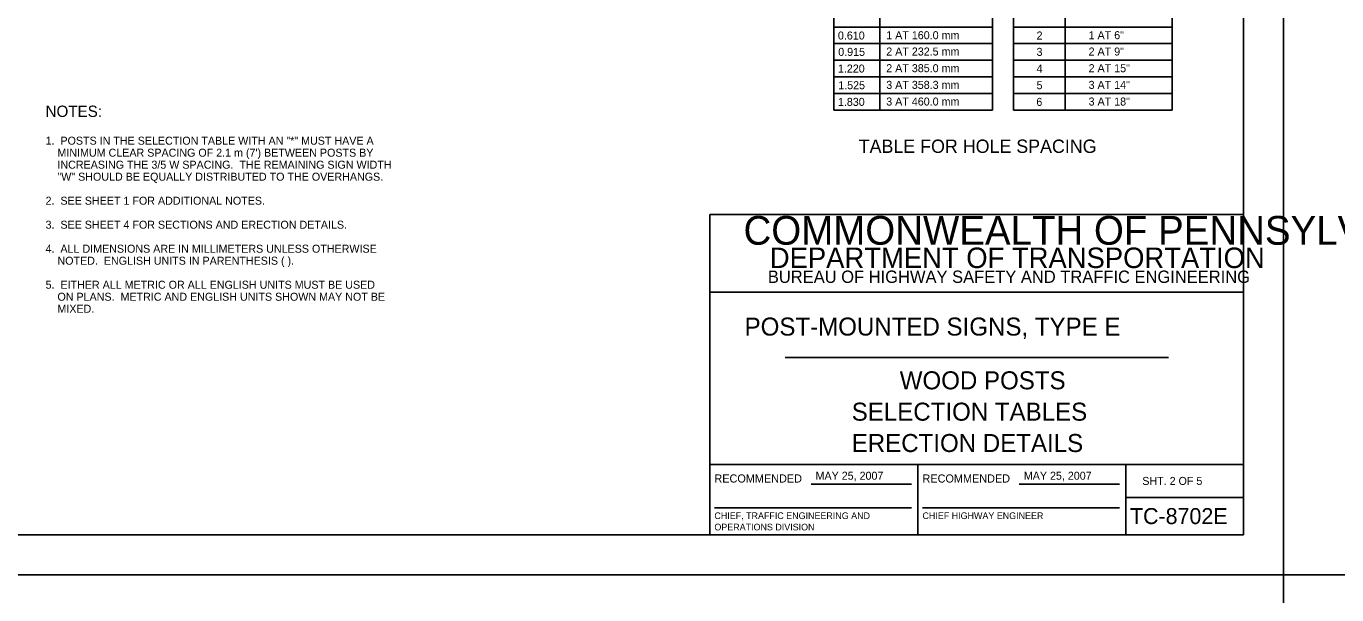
# Model space of a CAD drawing. Extents: x -1958 to 628, y -879 to 309.
# Drawn here: x -747.7 to -256.4, y -292.1 to -78.9 of the extents above; entities that cross this region are included whole.
import ezdxf

# ---------------------------------------------------------------- set-up
doc = ezdxf.new("R2010")
doc.units = 0
for name, color, linetype in [('1', 7, 'Continuous'), ('2', 7, 'Continuous'), ('3', 7, 'Continuous'), ('4', 7, 'Continuous'), ('PLT-BNDY', 7, 'Continuous')]:
    doc.layers.add(name, color=color, linetype=linetype)

msp = doc.modelspace()

# ---------------------------------------------------------------- linework, layer by layer
at = {"layer": '1'}
for p, q in [((-291.39, -269.56), (-291.39, 294.44)), ((-491.39, -269.56), (-491.39, -149.56)), ((-491.39, -149.56), (-291.39, -149.56)), ((-291.39, -178.56), (-491.39, -178.56)), ((-463.14, -203.06), (-319.51, -203.06)), ((-491.39, -243.19), (-291.39, -243.19)), ((-413.39, -243.19), (-413.39, -269.56)), ((-335.51, -269.56), (-335.51, -243.19)), ((-453.45, -250.62), (-415.83, -250.62)), ((-375.45, -250.62), (-337.83, -250.62)), ((-489.7, -259.51), (-415.83, -259.51)), ((-411.7, -259.51), (-337.83, -259.51)), ((-335.51, -255.56), (-291.39, -255.56)), ((-291.39, -269.56), (-1077.39, -269.56)), ((-1077.39, -269.56), (-491.39, -269.56))]:
    msp.add_line(p, q, dxfattribs=at)
at = {"layer": '2'}
for p, q in [((-444.9, -110.4), (-444.9, -60.53)), ((-385.4, -110.4), (-385.4, -60.53)), ((-377.63, -110.4), (-377.63, -60.53)), ((-318.13, -110.4), (-318.13, -60.53)), ((-427.65, -110.4), (-427.65, -73.03)), ((-358.24, -110.4), (-358.24, -73.03)), ((-385.4, -79.28), (-444.9, -79.28)), ((-318.13, -79.28), (-377.63, -79.28)), ((-385.4, -85.4), (-444.9, -85.4)), ((-318.13, -85.4), (-377.63, -85.4)), ((-385.4, -91.65), (-444.9, -91.65)), ((-318.13, -91.65), (-377.63, -91.65)), ((-385.4, -97.9), (-444.9, -97.9)), ((-318.13, -97.9), (-377.63, -97.9)), ((-385.4, -104.15), (-444.9, -104.15)), ((-318.13, -104.15), (-377.63, -104.15)), ((-385.4, -110.4), (-444.9, -110.4)), ((-318.13, -110.4), (-377.63, -110.4))]:
    msp.add_line(p, q, dxfattribs=at)
at = {"layer": 'PLT-BNDY'}
for points in [[(-1117.39, 309.44), (-276.39, 309.44), (-276.39, -284.56), (-1117.39, -284.56)], [(-276.39, 309.44), (564.61, 309.44), (564.61, -284.56), (-276.39, -284.56)], [(-1117.39, -284.56), (-276.39, -284.56), (-276.39, -878.56), (-1117.39, -878.56)]]:
    msp.add_lwpolyline(points, close=True, dxfattribs=at)

# ---------------------------------------------------------------- texts
at = {"layer": '1'}
for s, height, p in [('COMMONWEALTH OF PENNSYLVANIA', 10.7827, (-478.79, -160.83)), ('DEPARTMENT OF TRANSPORTATION', 7.6838, (-468.93, -169.58)), ('BUREAU OF HIGHWAY SAFETY AND TRAFFIC ENGINEERING', 4.6252, (-469.66, -175.15)), ('POST-MOUNTED SIGNS, TYPE E', 6.7492, (-478.39, -194.89)), ('WOOD POSTS', 6.75, (-420.23, -215.04)), ('SELECTION TABLES', 6.75, (-438.23, -226.79)), ('ERECTION DETAILS', 6.75, (-438.23, -238.54)), ('RECOMMENDED', 3.048, (-489.7, -249.99)), ('RECOMMENDED', 3.048, (-411.7, -249.99)), ('SHT. 2 OF 5', 3, (-329.3, -250.88)), ('TC-8702E', 6, (-333.91, -265.56)), ('CHIEF, TRAFFIC ENGINEERING AND', 2.5, (-489.7, -263.68)), ('CHIEF HIGHWAY ENGINEER', 2.5, (-411.7, -263.68)), ('OPERATIONS DIVISION', 2.5, (-489.7, -267.93))]:
    msp.add_text(s, height=height, dxfattribs=at).set_placement(p)
at = {"layer": '2'}
for p in [(-451.78, -248.93), (-373.71, -248.93)]:
    msp.add_text('MAY 25, 2007', height=3, dxfattribs=at).set_placement(p)
at = {"layer": '3'}
for s, height, p in [('0.610', 3, (-443.4, -83.9)), ('1 AT 160.0 mm', 3, (-425.28, -83.78)), ('2', 3, (-368.93, -83.9)), ('1 AT 6"', 3, (-349.42, -83.78)), ('0.915', 3, (-443.28, -90.03)), ('2 AT 232.5 mm', 3, (-425.28, -89.9)), ('3', 3, (-368.94, -90.03)), ('2 AT 9"', 3, (-349.42, -89.9)), ('1.220', 3, (-443.4, -96.28)), ('2 AT 385.0 mm', 3, (-425.28, -96.15)), ('4', 3, (-368.93, -96.28)), ('2 AT 15"', 3, (-349.42, -96.15)), ('1.525', 3, (-443.28, -102.53)), ('3 AT 358.3 mm', 3, (-425.28, -102.4)), ('5', 3, (-368.94, -102.53)), ('3 AT 14"', 3, (-349.42, -102.4)), ('1.830', 3, (-443.4, -108.78)), ('3 AT 460.0 mm', 3, (-425.28, -108.65)), ('6', 3, (-369.01, -108.78)), ('3 AT 18"', 3, (-349.42, -108.65)), ('NOTES:', 4.25, (-740.43, -112.93)), ('TABLE FOR HOLE SPACING', 5, (-435.61, -126.41))]:
    msp.add_text(s, height=height, dxfattribs=at).set_placement(p)
at = {"layer": '4'}
for s, p in [('1.  POSTS IN THE SELECTION TABLE WITH AN "*" MUST HAVE A', (-740.44, -123.33)), ("    MINIMUM CLEAR SPACING OF 2.1 m (7') BETWEEN POSTS BY", (-740.44, -127.83)), ('    INCREASING THE 3/5 W SPACING.  THE REMAINING SIGN WIDTH', (-740.44, -132.33)), ('    "W" SHOULD BE EQUALLY DISTRIBUTED TO THE OVERHANGS.', (-740.44, -136.83)), ('2.  SEE SHEET 1 FOR ADDITIONAL NOTES.', (-740.44, -145.83)), ('3.  SEE SHEET 4 FOR SECTIONS AND ERECTION DETAILS.', (-740.44, -154.83)), ('4.  ALL DIMENSIONS ARE IN MILLIMETERS UNLESS OTHERWISE', (-740.44, -163.83)), ('    NOTED.  ENGLISH UNITS IN PARENTHESIS ( ).', (-740.44, -168.33)), ('5.  EITHER ALL METRIC OR ALL ENGLISH UNITS MUST BE USED', (-740.44, -177.33)), ('    ON PLANS.  METRIC AND ENGLISH UNITS SHOWN MAY NOT BE', (-740.44, -181.83)), ('    MIXED.', (-740.44, -186.33))]:
    msp.add_text(s, height=3, dxfattribs=at).set_placement(p)

doc.saveas('drawing.dxf')
